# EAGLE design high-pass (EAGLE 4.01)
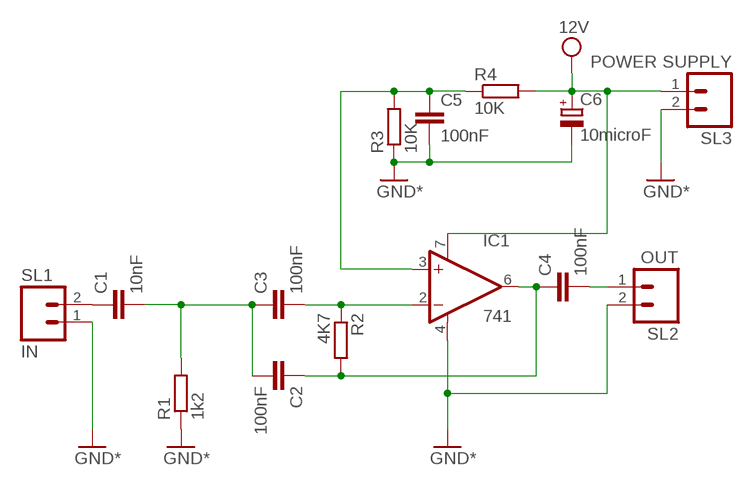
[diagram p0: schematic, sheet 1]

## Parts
C1  10nF  C-EUC0603  [C0603]
C2  100nF  C-EUC0603  [C0603]
C3  100nF  C-EUC0603  [C0603]
C4  100nF  C-EUC0603  [C0603]
C5  100nF  C-EUC0805  [C0805]
C6  10microF  CPOL-EUCT3528  [CT3528]
IC1  741  OPA237U  [SO-08]
R1  1k2  R-EU_R1206  [R1206]
R2  4K7  R-EU_R1206  [R1206]
R3  10K  R-EU_R1206  [R1206]
R4  10K  R-EU_R1206  [R1206]
SL1  IN  M02  [02P]
SL2  OUT  M02  [02P]
SL3  POWER SUPPLY  M02  [02P]

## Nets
GND: C5.1 C6.- IC1.4(V-) R1.1 R3.1 SL1.1 SL2.2 SL3.2 ; supply symbol labelled GND*
N$1: C5.2 IC1.3(+IN) R3.2 R4.1
N$2: C4.1 SL2.1
N$3: C1.1 C2.1 C3.2 R1.2
N$4: C2.2 C4.2 IC1.6(OUT) R2.2
N$5: C1.2 SL1.2
N$6: C3.1 IC1.2(-IN) R2.1
VCC: C6.+ IC1.7(V+) R4.2 SL3.1 ; supply symbol labelled 12V

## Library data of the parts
C1-C5 = rcl:C-EU: CAPACITOR, European symbol
C6 = rcl:CPOL-EU: POLARIZED CAPACITOR, European symbol
IC1 = burr-brown:OPA237U: BURR-BROWN
R1-R4 = rcl:R-EU_: RESISTOR, European symbol
SL1-SL3 = con-amp-quick:M02: AMP QUICK CONNECTOR

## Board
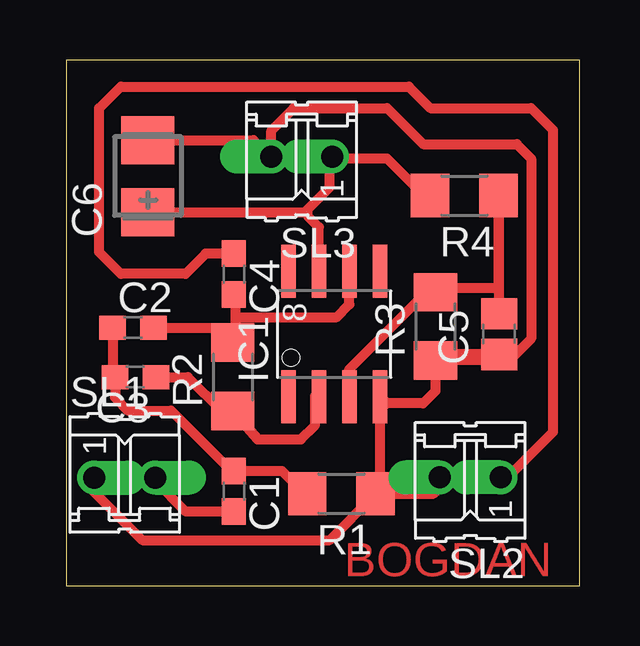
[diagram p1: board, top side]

Size 21.41 x 21.91 mm. Coordinates in mm from the lower left corner, seen from the top.
Outline: 0,0 21.41,0 21.41,21.91 0,21.91 0,0
Copper layers used: Top

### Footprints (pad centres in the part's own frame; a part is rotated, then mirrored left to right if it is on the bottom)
C0603 = smd 1.1 x 1: 1 -0.85,0; 2 0.85,0
C0805 = smd 1.3 x 1.5: 1 -0.85,0; 2 0.85,0
CT3528 = smd 2 x 2.2: + -1.5,0; - 1.5,0
SO-08 = smd 0.61 x 2.21: 1 -1.905,-2.616; 2 -0.635,-2.616; 3 0.635,-2.616; 4 1.905,-2.616; 5 1.905,2.616; 6 0.635,2.616; 7 -0.635,2.616; 8 -1.905,2.616
R1206 = smd 1.6 x 1.803: 1 -1.422,0; 2 1.422,0
02P = drill 0.914 offset: 1 -1.27,0; 2 1.27,0

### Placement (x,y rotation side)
C1  6.99,3.94 270 top
C2  2.79,10.75 0 top
C3  2.89,8.7 180 top
C4  6.99,12.99 270 top
C5  18.04,10.49 90 top
C6  3.41,17.07 90 top
IC1  11.17,10.49 0 top
R1  11.47,3.84 180 top
R2  6.95,8.71 90 top
R3  15.39,10.81 90 top
R4  16.59,16.26 180 top
SL1  2.44,4.51 0 top
SL2  16.84,4.52 180 top
SL3  9.82,17.88 180 top

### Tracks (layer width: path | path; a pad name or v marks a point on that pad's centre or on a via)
GND
  Top 0.406: R3.1 15.19,9.39 15.18,9.4 15.42,9.64 C5.1 | R3.1 15.39,8.11 14.88,7.6 13.38,7.6 13.08,7.9 13.07,7.89 IC1.4 13.07,3.7 | 13.07,3.7 12.94,3.84 R1.1 | 13.07,3.7 13.08,3.7 | SL2.2 15.78,4.3 15.32,3.84 R1.1 | SL1.1 1.17,3.91 3.18,1.9 10.98,1.9 12.89,3.81 R1.1 | 8.58,17.8 8.55,17.83 | 8.55,17.83 SL3.2 8.55,18.97 9.48,19.9 13.38,19.9 14.88,18.4 18.78,18.4 19.38,17.8 19.38,10.3 18.48,9.4 15.48,9.4 15.47,9.39 R3.1 | C6.- 7.81,18.57 8.55,17.83
N$1
  Top 0.406: 18.18,16.3 18.14,16.26 | 18.14,16.26 R4.1 18.01,12.53 17.88,12.4 15.48,12.4 15.39,12.31 R3.2 15.31,12.23 15.18,12.1 14.88,12.1 11.8,9.02 IC1.3 | C5.2 18.04,16.16 18.14,16.26
N$2
  Top 0.406: C4.1 5.82,13.84 4.98,13 2.28,13 1.38,13.9 1.38,19.9 2.28,20.8 14.28,20.8 15.18,19.9 19.38,19.9 20.28,19 20.28,6.4 18.18,4.3 18.11,4.37 SL2.1
N$3
  Top 0.406: 7.08,4.6 6.99,4.69 C1.1 | 10.05,3.73 10.08,3.7 | 10.05,3.73 R1.2 | C1.1 8.99,4.79 10.05,3.73 | C2.1 1.94,8.84 2.04,8.74 C3.2 2.04,7.84 2.58,7.3 4.38,7.3 6.89,4.79 C1.1
N$4
  Top 0.406: IC1.6 11.8,11.72 11.28,11.2 7.08,11.2 | C2.2 6.93,10.75 7.08,10.9 | C4.2 7.04,12.14 7.08,12.1 7.08,11.2 | 7.08,10.9 7.08,11.2 | R2.2 6.95,10.77 7.08,10.9
N$5
  Top 0.406: SL1.2 3.71,4.37 4.99,3.09 C1.2
N$6
  Top 0.406: IC1.2 10.38,7.9 10.38,6.7 9.78,6.1 7.98,6.1 R2.1 6.78,7.3 6.48,7.3 5.08,8.7 C3.1
VCC
  Top 0.406: C6.+ 9.95,15.57 10.98,16.6 | IC1.7 10.53,14.95 10.08,15.4 10.08,15.7 10.98,16.6 | 10.98,16.6 10.98,17.5 11.28,17.8 | R4.2 14.92,16.26 13.38,17.8 11.28,17.8 | 11.28,17.8 11.2,17.88 SL3.1

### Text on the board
Top: BOGDAN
